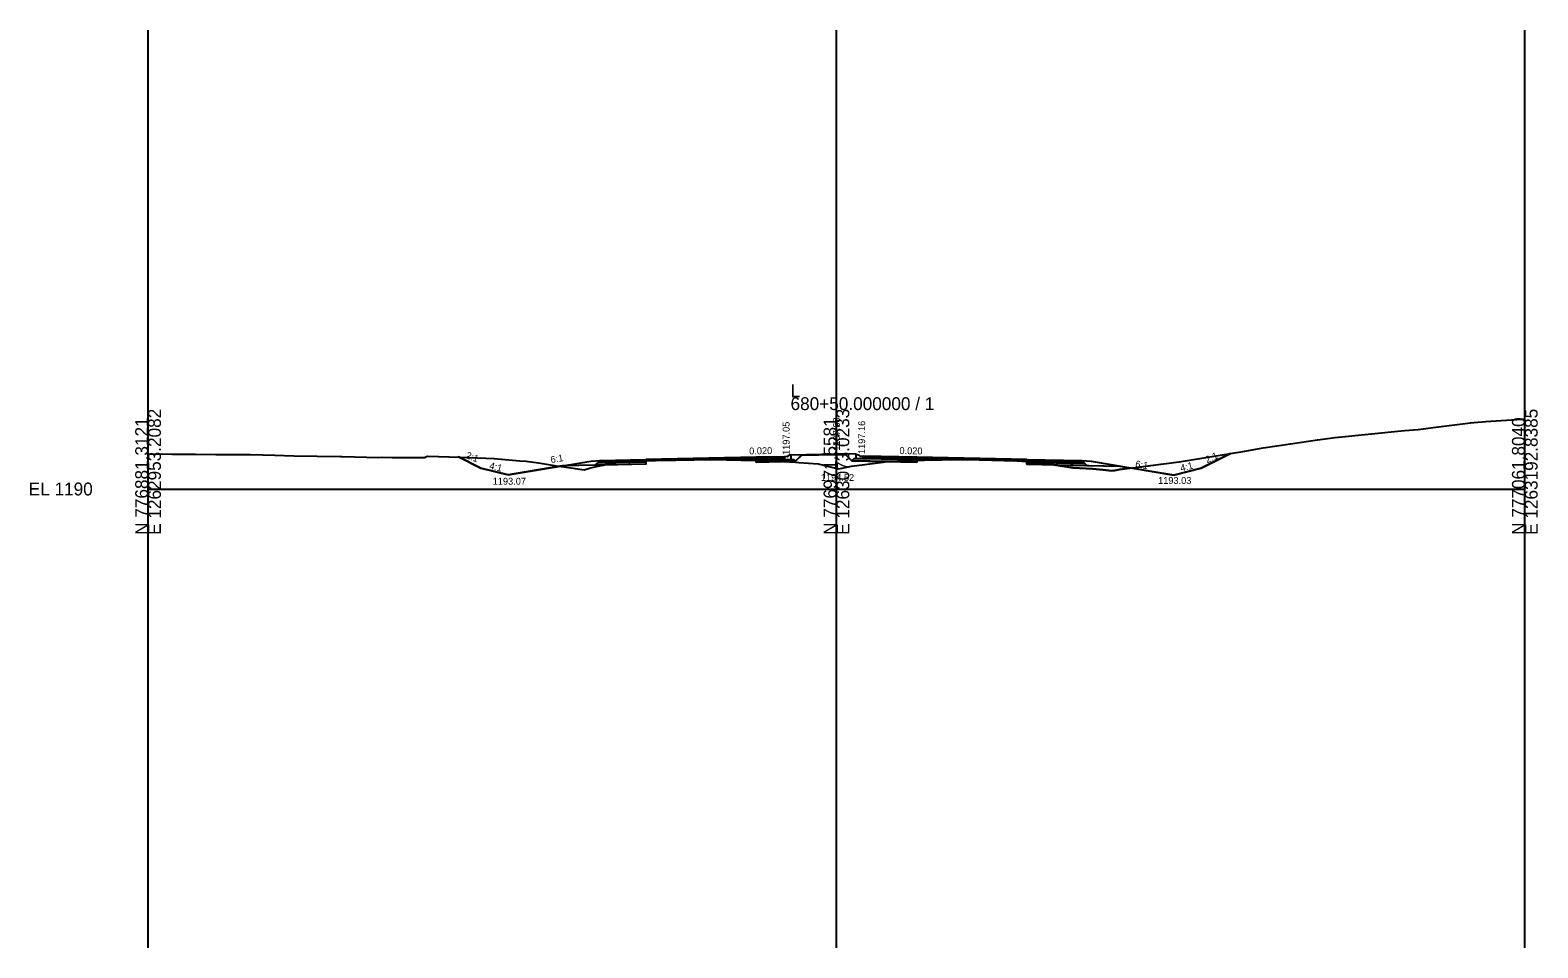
# Model space of a CAD drawing. Extents: x -41 to 1262860, y -100 to 777489.
# Drawn here: x 474.3 to 802.8, y 3405 to 3605 of the extents above; entities that cross this region are included whole.
import ezdxf

# ---------------------------------------------------------------- set-up
doc = ezdxf.new("R2010")
doc.units = 0
for name, color, linetype in [('Exist Cross Section Cell', 7, 'Continuous'), ('Exist XS Center Line Elevation Label', 7, 'Continuous'), ('Exist XS Ground Line', 7, 'Continuous'), ('Prop CMT Pvmt Course 1', 7, 'Continuous'), ('Prop CMT Pvmt Surface', 7, 'Continuous'), ('Prop CMT Shld Paved Course 1', 7, 'Continuous'), ('Prop CMT Shld Paved Course 2', 7, 'Continuous'), ('Prop CMT Shld Paved Course 4', 7, 'Continuous'), ('Prop CMT Subgrade Earthwork', 7, 'Continuous'), ('Prop Conc Curb and Gutter', 7, 'Continuous'), ('Prop Conc Island Cover', 7, 'Continuous'), ('Prop XS Ditch Standard Text', 7, 'Continuous'), ('Prop XS Earthwork Shape', 7, 'Continuous'), ('Prop XS Elevation Labels', 7, 'Continuous'), ('Prop XS Exc Vertical Line 1', 7, 'Continuous'), ('Prop XS Exc Vertical Line 2', 7, 'Continuous'), ('Prop XS Exc Vertical Line 3', 7, 'Continuous'), ('Prop XS Finish Grade', 7, 'Continuous'), ('Prop XS Hydro Elevations', 7, 'Continuous'), ('Prop XS SE Text', 7, 'Continuous'), ('Prop XS Side Slope Text', 7, 'Continuous'), ('Scratch_Level_4', 7, 'Continuous'), ('Scratch_Level_6', 7, 'Continuous')]:
    doc.layers.add(name, color=color, linetype=linetype)

msp = doc.modelspace()

# ---------------------------------------------------------------- linework, layer by layer
at = {"layer": 'Exist Cross Section Cell'}
for p, q in [((650, 3505), (650, 3525)), ((500, 3505), (650, 3505)), ((650, 3505), (800, 3505))]:
    msp.add_line(p, q, dxfattribs=at)
at = {"layer": 'Exist XS Ground Line'}
msp.add_lwpolyline([(500, 3512.68), (505.26, 3512.59), (508.54, 3512.59), (510.35, 3512.59), (514.74, 3512.53), (522.22, 3512.51), (527.63, 3512.4), (531.75, 3512.25), (541.95, 3512.07), (542.14, 3512.07), (542.24, 3512.07), (542.28, 3512.07), (550.31, 3511.9), (551.16, 3511.91), (553.21, 3511.87), (560.24, 3511.85), (560.65, 3512.05), (560.89, 3512.18), (568.1, 3511.97), (569.99, 3511.9), (575.41, 3511.65), (581.02, 3511.17), (582.4, 3511.04), (585.07, 3510.67), (589.03, 3510.05), (592.1, 3509.61), (595.01, 3509.15), (596.19, 3509.52), (598.01, 3509.94), (600.69, 3510.53), (601.96, 3510.8), (605.99, 3510.92), (607.11, 3511.01), (607.49, 3511.04), (610.56, 3511.26), (613.42, 3511.29), (622.92, 3511.4), (632.64, 3511.18), (635.33, 3511.13), (637.21, 3511.05), (639.79, 3510.93), (641.08, 3510.83), (641.79, 3510.77), (643.88, 3510.66), (646.01, 3510.5), (649.19, 3509.72), (650.48, 3509.4), (651.26, 3509.55), (653.3, 3509.99), (660.16, 3510.86), (661.1, 3510.96), (661.59, 3511.04), (665.02, 3511.22), (665.32, 3511.23), (676.68, 3511.4), (677.5, 3511.42), (678.31, 3511.4), (689.34, 3511.12), (692.94, 3510.89), (693.22, 3510.88), (694.08, 3510.8), (700.64, 3509.76), (700.65, 3509.76), (701.53, 3509.62), (701.61, 3509.62), (705.79, 3509.4), (708.09, 3509.15), (709.92, 3508.93), (710.65, 3509.01), (711.71, 3509.25), (720.69, 3510.41), (721.86, 3510.54), (724.67, 3510.9), (738.99, 3513.23), (743.01, 3513.97), (748.96, 3514.84), (754.83, 3515.69), (758.64, 3516.23), (773.81, 3517.73), (776.73, 3517.99), (780.58, 3518.45), (788.2, 3519.43), (788.86, 3519.46), (791.49, 3519.74), (799.38, 3520.19), (800, 3520.22)], dxfattribs=at)
at = {"layer": 'Prop CMT Pvmt Course 1'}
for p, q in [((638.65, 3511.78), (638.65, 3512.03)), ((655.8, 3512.14), (655.8, 3511.89)), ((632.5, 3511.66), (638.65, 3511.78)), ((667.5, 3511.66), (655.8, 3511.89))]:
    msp.add_line(p, q, dxfattribs=at)
for points in [[(608.5, 3511.43), (608.5, 3511.18), (632.5, 3511.66), (632.5, 3511.66), (632.5, 3511.91), (632.5, 3511.91), (632.5, 3511.91), (608.5, 3511.43), (608.5, 3511.43)], [(691.5, 3511.43), (691.5, 3511.43), (667.5, 3511.91), (667.5, 3511.91), (667.5, 3511.91), (667.5, 3511.66), (667.5, 3511.66), (691.5, 3511.18), (691.5, 3511.43)]]:
    msp.add_lwpolyline(points, dxfattribs=at)
at = {"layer": 'Prop CMT Pvmt Surface'}
for p, q in [((638.65, 3512.03), (632.5, 3511.91)), ((667.5, 3511.91), (655.8, 3512.14)), ((598.5, 3511.23), (608.5, 3511.43)), ((608.5, 3511.43), (632.5, 3511.91)), ((667.5, 3511.91), (691.5, 3511.43)), ((691.5, 3511.43), (703.5, 3511.19))]:
    msp.add_line(p, q, dxfattribs=at)
at = {"layer": 'Prop CMT Shld Paved Course 1'}
for p, q in [((598.24, 3510.98), (598.5, 3511.23)), ((608.5, 3511.18), (598.24, 3510.98)), ((604.5, 3511.35), (604.5, 3511.35)), ((608.5, 3511.43), (608.5, 3511.43)), ((608.5, 3511.43), (608.5, 3511.43)), ((608.5, 3511.43), (608.5, 3511.18)), ((608.5, 3511.18), (608.5, 3511.18)), ((691.5, 3511.43), (691.5, 3511.43)), ((691.5, 3511.43), (691.5, 3511.43)), ((691.5, 3511.43), (691.5, 3511.18)), ((691.5, 3511.18), (691.5, 3511.18)), ((691.5, 3511.18), (703.76, 3510.94)), ((695.5, 3511.35), (695.5, 3511.35)), ((703.76, 3510.94), (703.5, 3511.19))]:
    msp.add_line(p, q, dxfattribs=at)
at = {"layer": 'Prop CMT Shld Paved Course 2'}
for p, q in [((597.9, 3510.63), (598.24, 3510.98)), ((608.5, 3510.85), (597.9, 3510.63)), ((604.24, 3511.1), (604.24, 3511.1)), ((610.56, 3511.22), (608.5, 3511.18)), ((608.5, 3511.11), (609.8, 3511.21)), ((608.5, 3511.18), (608.5, 3511.18)), ((608.5, 3511.18), (608.5, 3511.18)), ((608.5, 3511.18), (608.5, 3510.85)), ((608.5, 3511.18), (608.5, 3511.18)), ((608.5, 3511.18), (608.5, 3511.18)), ((608.5, 3511.18), (608.5, 3511.11)), ((608.5, 3511.11), (608.5, 3511.11)), ((608.5, 3510.85), (608.5, 3510.85)), ((609.8, 3511.21), (610.56, 3511.22)), ((609.8, 3511.21), (609.8, 3511.21)), ((613.42, 3511.28), (610.56, 3511.22)), ((610.56, 3511.22), (613.42, 3511.28)), ((610.56, 3511.22), (610.56, 3511.22)), ((610.56, 3511.22), (610.56, 3511.22)), ((622.92, 3511.47), (613.42, 3511.28)), ((613.42, 3511.28), (614.98, 3511.31)), ((613.42, 3511.28), (613.42, 3511.28)), ((613.42, 3511.28), (613.42, 3511.28)), ((614.98, 3511.31), (622.92, 3511.4)), ((614.98, 3511.31), (614.98, 3511.31)), ((632.5, 3511.66), (622.92, 3511.47)), ((622.92, 3511.47), (622.92, 3511.47)), ((622.92, 3511.47), (622.92, 3511.47)), ((622.92, 3511.4), (622.92, 3511.4)), ((622.92, 3511.4), (622.92, 3511.4)), ((622.92, 3511.4), (629.14, 3511.26)), ((629.14, 3511.26), (632.5, 3511.33)), ((629.14, 3511.26), (629.14, 3511.26)), ((629.14, 3511.26), (629.14, 3511.26)), ((632.5, 3511.33), (632.5, 3511.66)), ((632.5, 3511.66), (632.5, 3511.66)), ((632.5, 3511.66), (632.5, 3511.66)), ((632.5, 3511.33), (638.65, 3511.45)), ((638.65, 3511.78), (638.65, 3511.45)), ((638.65, 3511.45), (638.65, 3511.45)), ((655.8, 3511.56), (655.8, 3511.89)), ((667.5, 3511.33), (655.8, 3511.56)), ((676.68, 3511.48), (667.5, 3511.66)), ((667.5, 3511.66), (667.5, 3511.66)), ((667.5, 3511.66), (667.5, 3511.66)), ((667.5, 3511.66), (667.5, 3511.33)), ((667.5, 3511.33), (667.5, 3511.33)), ((667.5, 3511.33), (669.26, 3511.29)), ((669.26, 3511.29), (676.68, 3511.4)), ((669.26, 3511.29), (669.26, 3511.29)), ((677.5, 3511.46), (676.68, 3511.48)), ((676.68, 3511.48), (676.68, 3511.48)), ((676.68, 3511.4), (677.5, 3511.42)), ((676.68, 3511.4), (676.68, 3511.4)), ((678.31, 3511.44), (677.5, 3511.46)), ((677.5, 3511.42), (678.31, 3511.4)), ((689.34, 3511.22), (678.31, 3511.44)), ((678.31, 3511.44), (678.31, 3511.44)), ((678.31, 3511.4), (678.31, 3511.4)), ((678.31, 3511.4), (689.34, 3511.12)), ((691.5, 3511.18), (689.34, 3511.22)), ((689.34, 3511.22), (689.34, 3511.22)), ((689.34, 3511.22), (689.34, 3511.22)), ((689.34, 3511.12), (689.34, 3511.12)), ((689.34, 3511.12), (689.34, 3511.12)), ((689.34, 3511.12), (691.5, 3510.99)), ((691.5, 3511.18), (691.5, 3511.18)), ((691.5, 3511.18), (691.5, 3511.18)), ((691.5, 3511.18), (691.5, 3510.85)), ((691.5, 3510.99), (691.5, 3511.18)), ((691.5, 3511.18), (691.5, 3511.18)), ((691.5, 3511.18), (691.5, 3511.18)), ((691.5, 3510.99), (691.5, 3510.99)), ((691.5, 3510.85), (691.5, 3510.85)), ((691.5, 3510.85), (704.1, 3510.59)), ((704.1, 3510.59), (703.76, 3510.94))]:
    msp.add_line(p, q, dxfattribs=at)
at = {"layer": 'Prop CMT Shld Paved Course 4'}
for p, q in [((597.44, 3510.17), (597.9, 3510.63)), ((608.5, 3510.39), (597.44, 3510.17)), ((603.4, 3510.74), (603.4, 3510.74)), ((603.9, 3510.75), (603.9, 3510.75)), ((608.5, 3510.85), (608.5, 3510.85)), ((608.5, 3510.85), (608.5, 3510.85)), ((608.5, 3510.85), (608.5, 3510.39)), ((629.14, 3511.26), (632.5, 3511.19)), ((632.5, 3511.33), (632.5, 3510.87)), ((632.5, 3510.87), (641.1, 3511.04)), ((638.65, 3511.45), (640.65, 3511.49)), ((640.65, 3511.49), (641.1, 3511.04)), ((653.8, 3511.6), (653.35, 3511.15)), ((653.35, 3511.15), (667.5, 3510.87)), ((655.8, 3511.56), (653.8, 3511.6)), ((667.5, 3511.33), (667.5, 3510.87)), ((669.26, 3511.29), (667.5, 3511.27)), ((691.5, 3510.85), (691.5, 3510.85)), ((691.5, 3510.85), (691.5, 3510.85)), ((691.5, 3510.85), (691.5, 3510.39)), ((691.5, 3510.39), (704.56, 3510.13)), ((704.56, 3510.13), (704.1, 3510.59))]:
    msp.add_line(p, q, dxfattribs=at)
at = {"layer": 'Prop CMT Subgrade Earthwork'}
for p, q in [((641.1, 3511.04), (642.59, 3512.53)), ((653.35, 3511.15), (651.86, 3512.64)), ((608.5, 3510.39), (590.22, 3510.02)), ((608.5, 3511.11), (608.5, 3510.39)), ((632.5, 3511.19), (632.5, 3510.87)), ((641.1, 3511.04), (632.5, 3510.87)), ((653.35, 3511.15), (667.5, 3510.87)), ((667.5, 3510.87), (667.5, 3511.27)), ((691.5, 3510.99), (691.5, 3510.39)), ((691.5, 3510.39), (711.78, 3509.98))]:
    msp.add_line(p, q, dxfattribs=at)
at = {"layer": 'Prop Conc Curb and Gutter'}
for p, q in [((639.34, 3512.05), (638.65, 3512.03)), ((638.65, 3512.03), (638.65, 3511.45)), ((639.4, 3512.12), (639.4, 3512.11)), ((640.15, 3512.48), (639.5, 3512.26)), ((640.15, 3511.48), (640.15, 3512.48)), ((654.3, 3512.59), (654.95, 3512.37)), ((654.3, 3511.59), (654.3, 3512.59)), ((655.05, 3512.24), (655.05, 3512.22)), ((655.11, 3512.16), (655.8, 3512.14)), ((655.8, 3511.56), (655.8, 3512.14)), ((638.65, 3511.45), (640.15, 3511.48)), ((640.15, 3511.48), (640.15, 3511.48)), ((655.8, 3511.56), (654.3, 3511.59))]:
    msp.add_line(p, q, dxfattribs=at)
for centre, radius, start, end in [((639.34, 3512.11), 0.0625, 271.1458, 360), ((639.55, 3512.12), 0.146, 108.435, 180), ((654.9, 3512.24), 0.146, 0, 71.565), ((655.11, 3512.22), 0.0625, 180, 268.8542)]:
    msp.add_arc(centre, radius, start, end, dxfattribs=at)
at = {"layer": 'Prop Conc Island Cover'}
for p, q in [((640.15, 3512.48), (650, 3512.68)), ((640.15, 3512.21), (640.15, 3512.21)), ((654.3, 3512.59), (650, 3512.68))]:
    msp.add_line(p, q, dxfattribs=at)
at = {"layer": 'Prop XS Earthwork Shape'}
for points in [[(641.79, 3510.77), (643.88, 3510.66), (646.01, 3510.5), (649.19, 3509.72), (650.48, 3509.4), (651.26, 3509.55), (653.3, 3509.99), (660.16, 3510.86), (661.1, 3510.96), (661.31, 3510.99), (653.35, 3511.15), (652.11, 3512.38), (650, 3512.43), (642.34, 3512.27), (641.1, 3511.04), (638.49, 3510.99), (639.79, 3510.93), (641.08, 3510.83)], [(721.86, 3510.54), (724.67, 3510.9), (735.89, 3512.73), (729.5, 3509.53), (723.5, 3508.03), (714.23, 3509.57), (720.69, 3510.41)], [(581.02, 3511.17), (582.4, 3511.04), (585.07, 3510.67), (589.03, 3510.05), (589.76, 3509.95), (578.5, 3508.07), (572.5, 3509.57), (567.68, 3511.98), (568.1, 3511.97), (569.99, 3511.9), (575.41, 3511.65)], [(598.01, 3509.94), (599.21, 3510.2), (597.44, 3510.17), (590.22, 3510.02), (589.76, 3509.95), (592.1, 3509.61), (595.01, 3509.15), (596.19, 3509.52)], [(601.96, 3510.8), (605.99, 3510.92), (607.11, 3511.01), (607.49, 3511.04), (608.5, 3511.11), (608.5, 3510.39), (599.21, 3510.2), (600.69, 3510.53)], [(632.5, 3511.19), (632.64, 3511.18), (635.33, 3511.13), (637.21, 3511.05), (638.49, 3510.99), (632.5, 3510.87)], [(661.31, 3510.99), (661.59, 3511.04), (665.02, 3511.22), (665.32, 3511.23), (667.5, 3511.27), (667.5, 3510.87)], [(692.94, 3510.89), (693.22, 3510.88), (694.08, 3510.8), (697.41, 3510.27), (691.5, 3510.39), (691.5, 3510.99)], [(704.56, 3510.13), (711.78, 3509.98), (714.23, 3509.57), (711.71, 3509.25), (710.65, 3509.01), (709.92, 3508.93), (708.09, 3509.15), (705.79, 3509.4), (701.61, 3509.62), (701.53, 3509.62), (700.64, 3509.76), (697.41, 3510.27)]]:
    msp.add_lwpolyline(points, close=True, dxfattribs=at)
at = {"layer": 'Prop XS Exc Vertical Line 1'}
msp.add_line((500, 3405), (500, 3605), dxfattribs=at)
at = {"layer": 'Prop XS Exc Vertical Line 2'}
msp.add_line((650, 3405), (650, 3605), dxfattribs=at)
at = {"layer": 'Prop XS Exc Vertical Line 3'}
msp.add_line((800, 3405), (800, 3605), dxfattribs=at)
at = {"layer": 'Prop XS Finish Grade'}
for p, q in [((729.5, 3509.53), (735.89, 3512.73)), ((567.68, 3511.98), (572.5, 3509.57)), ((572.5, 3509.57), (578.5, 3508.07)), ((578.5, 3508.07), (596.5, 3511.07)), ((596.5, 3511.07), (598.5, 3511.23)), ((598.5, 3511.23), (597.44, 3510.17)), ((703.5, 3511.19), (705.5, 3511.03)), ((703.5, 3511.19), (704.56, 3510.13)), ((705.5, 3511.03), (723.5, 3508.03)), ((723.5, 3508.03), (729.5, 3509.53))]:
    msp.add_line(p, q, dxfattribs=at)
at = {"layer": 'Scratch_Level_4'}
msp.add_line((800, 3405), (800, 3605), dxfattribs=at)
at = {"layer": 'Scratch_Level_6'}
msp.add_line((500, 3405), (500, 3605), dxfattribs=at)

# ---------------------------------------------------------------- texts
at = {"layer": 'Exist Cross Section Cell'}
for s, p in [('L', (640, 3525)), ('680+50.000000 / 1', (640, 3522.2)), ('EL 1190', (474, 3503.6))]:
    msp.add_text(s, height=2.8, dxfattribs=at).set_placement(p)
for s, p in [('E 1262953.2082', (502.8, 3495)), ('E 1263073.0233', (652.8, 3495)), ('E 1263192.8385', (802.8, 3495)), ('N 776881.3121', (500, 3495)), ('N 776971.5581', (650, 3495)), ('N 777061.8040', (800, 3495))]:
    msp.add_text(s, height=2.8, rotation=90, dxfattribs=at).set_placement(p)
at = {"layer": 'Exist XS Center Line Elevation Label'}
msp.add_text('1194.52', height=1.5, dxfattribs=at).set_placement((646.61, 3506.77))
at = {"layer": 'Prop XS Ditch Standard Text'}
for s, p in [('1193.07', (575.1, 3505.94)), ('1193.03', (720.09, 3506.11))]:
    msp.add_text(s, height=1.5, dxfattribs=at).set_placement(p)
at = {"layer": 'Prop XS Elevation Labels'}
for s, p in [('1197.05', (639.79, 3512.42)), ('1197.16', (656.26, 3512.62))]:
    msp.add_text(s, height=1.5, rotation=90, dxfattribs=at).set_placement(p)
at = {"layer": 'Prop XS Hydro Elevations'}
msp.add_text('1197.68', height=1.5, rotation=90, dxfattribs=at).set_placement((650.75, 3513.34))
at = {"layer": 'Prop XS SE Text'}
for rotation, p in [(1.1458, (631, 3512.53)), (358.8542, (663.72, 3512.63))]:
    msp.add_text('0.020', height=1.5, rotation=rotation, dxfattribs=at).set_placement(p)
at = {"layer": 'Prop XS Side Slope Text'}
for s, rotation, p in [('2:1', 338.2726, (569.08, 3511.79)), ('6:1', 9.4623, (587.83, 3510.63)), ('2:1', 24.7387, (730.78, 3510.59)), ('4:1', 345.9638, (574.25, 3509.44)), ('6:1', 350.5377, (715.03, 3509.76)), ('4:1', 14.0362, (725.13, 3508.79))]:
    msp.add_text(s, height=1.5, rotation=rotation, dxfattribs=at).set_placement(p)

doc.saveas('drawing.dxf')
